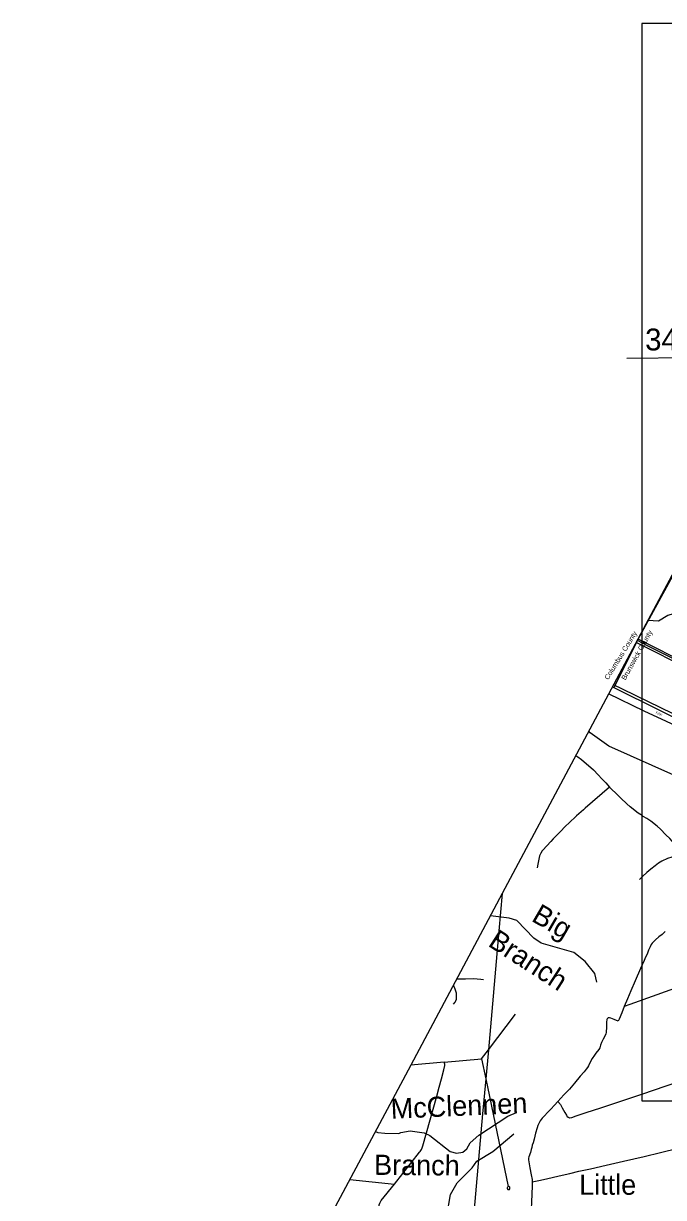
# Model space of a CAD drawing. Extents: x 2225501 to 2309677, y 165449 to 227696.
# Drawn here: x 2225501 to 2244504, y 188364 to 223234 of the extents above; entities that cross this region are included whole.
import ezdxf

# ---------------------------------------------------------------- set-up
doc = ezdxf.new("R2010")
doc.units = 0
for name, color, linetype in [('Black Area Fill Shapes', 7, 'Continuous'), ('Old_Level_3', 7, 'Continuous'), ('Old_Level_46', 7, 'Continuous'), ('Old_Level_51', 7, 'Continuous'), ('P_HYD_Default', 7, 'Continuous'), ('P_HYD_DRAINAGE_STR_TYPE_LABEL', 7, 'Continuous'), ('P_HYD_Drop_Inlet_Box_Type_A_48_Dia-Bottom_CELL', 7, 'Continuous'), ('P_HYD_Pipe_Pipe_Removal', 7, 'Continuous'), ('P_HYD_PIPE_RCP_CLASS IV_LABEL', 7, 'Continuous'), ('Prop Support', 7, 'Continuous'), ('Scratch_Level_1', 7, 'Continuous'), ('Scratch_Level_2', 7, 'Continuous'), ('Typical Terminator CELL', 7, 'Continuous')]:
    doc.layers.add(name, color=color, linetype=linetype)

msp = doc.modelspace()

# ---------------------------------------------------------------- linework, layer by layer
at = {"layer": 'Black Area Fill Shapes'}
for p, q in [((2243694, 204858), (2243706, 204852)), ((2243731, 204903), (2243720, 204908)), ((2239304, 192753), (2239226, 191885))]:
    msp.add_line(p, q, dxfattribs=at)
for points in [[(2243706, 204852), (2245312, 204032), (2246428, 203473)], [(2246388, 203562), (2245857, 203826), (2244049, 204743), (2243731, 204903)], [(2239717, 197394), (2239619, 196284), (2239304, 192753)], [(2239226, 191885), (2239134, 190846), (2238733, 186327), (2238520, 183900)]]:
    msp.add_lwpolyline(points, dxfattribs=at)
at = {"layer": 'Old_Level_3'}
for p, q in [((2243753, 204947), (2244835, 206921)), ((2243083, 203594), (2243706, 204852)), ((2243706, 204852), (2243731, 204903)), ((2243731, 204903), (2243753, 204947)), ((2246351, 203642), (2243753, 204947)), ((2243053, 203534), (2243083, 203594)), ((2239304, 192753), (2240113, 193811)), ((2237990, 192382), (2239100, 192487)), ((2239100, 192487), (2239304, 192753)), ((2239100, 192487), (2239226, 191885)), ((2237990, 192382), (2237003, 192299)), ((2239226, 191885), (2239895, 188693)), ((2235194, 188904), (2236512, 188764))]:
    msp.add_line(p, q, dxfattribs=at)
for points in [[(2241900, 201490), (2241962, 201455), (2242073, 201372), (2242427, 201063), (2242564, 200922), (2242673, 200799), (2242792, 200678), (2242901, 200547)], [(2242901, 200547), (2242182, 199924), (2242133, 199883), (2242061, 199817), (2241922, 199700), (2241696, 199486), (2241603, 199403), (2241423, 199216), (2241230, 199022), (2241159, 198940), (2240917, 198682), (2240897, 198658), (2240860, 198595), (2240824, 198515), (2240815, 198459), (2240792, 198363), (2240773, 198265), (2240757, 198157)], [(2245035, 198545), (2245000, 198613), (2244939, 198721), (2244878, 198808), (2244832, 198868), (2244687, 199027), (2244576, 199135), (2244417, 199300), (2244316, 199393), (2244131, 199538), (2244008, 199623), (2243904, 199678), (2243868, 199706), (2243755, 199777), (2243516, 199963), (2243415, 200052), (2243234, 200226), (2243161, 200304), (2242901, 200547)], [(2245035, 198545), (2244755, 198477), (2244622, 198432), (2244454, 198351), (2244357, 198296), (2244307, 198254), (2244254, 198215), (2244130, 198116), (2244011, 198015), (2243894, 197912), (2243795, 197806)], [(2244549, 196261), (2244465, 196180), (2244363, 196104), (2244270, 196017), (2244212, 195970), (2244171, 195921), (2244142, 195880), (2244107, 195813), (2244060, 195709), (2244014, 195595), (2243970, 195505), (2243929, 195400), (2243822, 195164), (2243662, 194801), (2243537, 194501), (2243435, 194268), (2243336, 194033)], [(2248862, 196001), (2248734, 195956), (2248175, 195758), (2247739, 195604), (2247355, 195470), (2246896, 195307), (2246495, 195162), (2246087, 195022), (2245680, 194876), (2245366, 194760), (2245110, 194667), (2244691, 194522), (2244168, 194335), (2243505, 194094), (2243336, 194033)], [(2238265, 194108), (2238319, 194170), (2238337, 194205), (2238354, 194253), (2238362, 194299), (2238353, 194437), (2238320, 194550), (2238268, 194673)], [(2239159, 194831), (2239079, 194840), (2238865, 194855), (2238623, 194853), (2238519, 194848), (2238363, 194852)], [(2243336, 194033), (2243267, 193845), (2243191, 193664), (2243157, 193606), (2243040, 193647), (2242941, 193688), (2242901, 193699), (2242860, 193699), (2242831, 193676), (2242819, 193653), (2242813, 193577), (2242808, 193432), (2242802, 193269), (2242796, 193222), (2242773, 193176), (2242714, 193071), (2242662, 192972), (2242633, 192890), (2242610, 192809), (2242581, 192757), (2242499, 192652), (2242453, 192588), (2242389, 192489), (2242319, 192361), (2242272, 192280), (2242249, 192227), (2242208, 192181), (2242144, 192093), (2242034, 191971), (2241859, 191762), (2241708, 191587), (2241540, 191410), (2241371, 191218)], [(2236512, 188764), (2237262, 189715), (2237279, 189734), (2237315, 189792), (2237336, 189840), (2237358, 189900), (2237774, 191373), (2237844, 191645), (2237916, 191890), (2237985, 192159), (2238014, 192281), (2238012, 192327), (2237990, 192382)], [(2241371, 191218), (2241441, 191130), (2241499, 191026), (2241574, 190892), (2241621, 190810), (2241644, 190764), (2241679, 190746), (2241714, 190735), (2241784, 190741), (2241912, 190787), (2242208, 190886), (2242639, 191031), (2243063, 191171), (2243447, 191299), (2243889, 191447), (2244558, 191674), (2245111, 191861), (2245434, 191961)], [(2241371, 191218), (2241269, 191109), (2241159, 190992), (2241060, 190885), (2240967, 190786), (2240903, 190719), (2240868, 190678), (2240842, 190646), (2240804, 190564), (2240769, 190500), (2240749, 190436), (2240705, 190271), (2240664, 190102), (2240629, 189991), (2240609, 189924), (2240594, 189852), (2240577, 189791), (2240551, 189703), (2240510, 189572), (2240498, 189537), (2240493, 189488), (2240501, 189421), (2240536, 189248), (2240571, 189039), (2240600, 188899), (2240609, 188826)], [(2240609, 188826), (2240804, 188868), (2241031, 188921), (2241409, 189005), (2241723, 189078), (2241993, 189142), (2242339, 189220), (2242802, 189328), (2243319, 189444), (2243933, 189587), (2244413, 189703), (2244942, 189831), (2245346, 189927), (2245789, 190035), (2246175, 190125), (2246487, 190198), (2246891, 190297), (2247333, 190404), (2247595, 190467)], [(2236251, 186169), (2236052, 186499), (2236001, 186602), (2235981, 186632), (2236065, 188146), (2236084, 188200), (2236124, 188273), (2236512, 188764)], [(2239895, 188693), (2239877, 188683), (2239867, 188669), (2239861, 188653), (2239861, 188635), (2239882, 188605), (2239903, 188602), (2239929, 188602), (2239941, 188620), (2239945, 188634), (2239945, 188652), (2239939, 188670), (2239921, 188688), (2239895, 188693)], [(2240609, 188826), (2240606, 188700), (2240594, 188470), (2240583, 188226), (2240577, 188031), (2240568, 187924), (2240545, 187694), (2240513, 187333), (2240490, 187057), (2240466, 186774), (2240458, 186565), (2240446, 186294), (2240434, 185986), (2240423, 185651), (2240414, 185395), (2240405, 185160), (2240402, 185003)]]:
    msp.add_lwpolyline(points, dxfattribs=at)
at = {"layer": 'Old_Level_46'}
for points in [[(2242986, 203531), (2247394, 201341), (2248933, 200581), (2250062, 200025), (2252258, 198936), (2253668, 198238), (2254159, 197994), (2254221, 197964), (2255278, 197443), (2256251, 196964), (2256280, 196950), (2256416, 196885), (2256553, 196820), (2256635, 196788), (2256781, 196739), (2256906, 196710), (2256941, 196701), (2256960, 196697)], [(2256957, 196790), (2256925, 196796), (2256832, 196817), (2256652, 196876), (2256591, 196902), (2256480, 196951), (2256339, 197006), (2256283, 197031), (2254542, 197924), (2254210, 198073), (2253787, 198278), (2252186, 199074), (2250122, 200128), (2248769, 200789), (2247375, 201476), (2243675, 203271), (2243284, 203458), (2243017, 203588)]]:
    msp.add_lwpolyline(points, dxfattribs=at)
at = {"layer": 'Old_Level_51'}
msp.add_lwpolyline([(2252865, 222076), (2251537, 219581), (2249903, 216515), (2248210, 213337), (2246231, 209621), (2243743, 204951), (2241922, 201533), (2239717, 197394), (2237003, 192299), (2234601, 187789), (2232019, 182943), (2229513, 178250), (2226734, 173036), (2226255, 172151), (2225501, 170758)], dxfattribs=at)
at = {"layer": 'P_HYD_Pipe_Pipe_Removal'}
msp.add_lwpolyline([(2243856, 191238), (2266254, 191238), (2266254, 223234), (2243856, 223234)], close=True, dxfattribs=at)
at = {"layer": 'P_HYD_PIPE_RCP_CLASS IV_LABEL'}
msp.add_line((2243413, 213298), (2249796, 213349), dxfattribs=at)
at = {"layer": 'Prop Support'}
for points in [[(2244041, 205510), (2244357, 205490), (2244629, 205665), (2244988, 205760)], [(2246788, 201402), (2246772, 201435), (2245793, 201943), (2243929, 202812), (2242874, 203320)], [(2245345, 200715), (2244811, 200912), (2242879, 201770), (2242326, 202164), (2242287, 202217)], [(2238069, 187818), (2238180, 188452), (2238378, 188796), (2238824, 189250), (2238965, 189444), (2239437, 189730), (2240057, 190259)]]:
    msp.add_lwpolyline(points, dxfattribs=at)
at = {"layer": 'Typical Terminator CELL'}
for points in [[(2242520, 194761), (2242467, 195018), (2242182, 195374), (2241845, 195640), (2240868, 195921), (2240651, 196070), (2240147, 196591), (2239921, 196665), (2239365, 196732)], [(2235952, 190327), (2236026, 190291), (2236233, 190271), (2236641, 190263), (2236700, 190298), (2236982, 190342), (2237399, 190288), (2237566, 190206), (2238170, 189735), (2238362, 189678), (2238545, 189714), (2238661, 189814), (2238768, 189989), (2239016, 190217), (2239877, 190784), (2240136, 190894)]]:
    msp.add_lwpolyline(points, dxfattribs=at)

# ---------------------------------------------------------------- texts
at = {"layer": 'P_HYD_Default'}
msp.add_text('Little', height=600, dxfattribs=at).set_placement((2241999, 188446))
at = {"layer": 'P_HYD_DRAINAGE_STR_TYPE_LABEL'}
msp.add_text("34° 20'", height=650, rotation=0.2163, dxfattribs=at).set_placement((2243961, 213522))
at = {"layer": 'P_HYD_Drop_Inlet_Box_Type_A_48_Dia-Bottom_CELL'}
for s, rotation, p in [('Columbus County', 58.4144, (2242866, 203725)), ('Brunswick County', 60.7886, (2243374, 203716))]:
    msp.add_text(s, height=150, rotation=rotation, dxfattribs=at).set_placement(p)
at = {"layer": 'Scratch_Level_1'}
for s, rotation, p in [('Big', 329.8911, (2240553, 196593)), ('Branch', 327.1771, (2239264, 195853)), ('McClennen', 2.5508, (2236417, 190699)), ('Branch', 359.4631, (2235907, 189039))]:
    msp.add_text(s, height=600, rotation=rotation, dxfattribs=at).set_placement(p)
at = {"layer": 'Scratch_Level_2'}
msp.add_text('FAP', height=75, rotation=334.9663, dxfattribs=at).set_placement((2244263, 202737))

doc.saveas('drawing.dxf')
